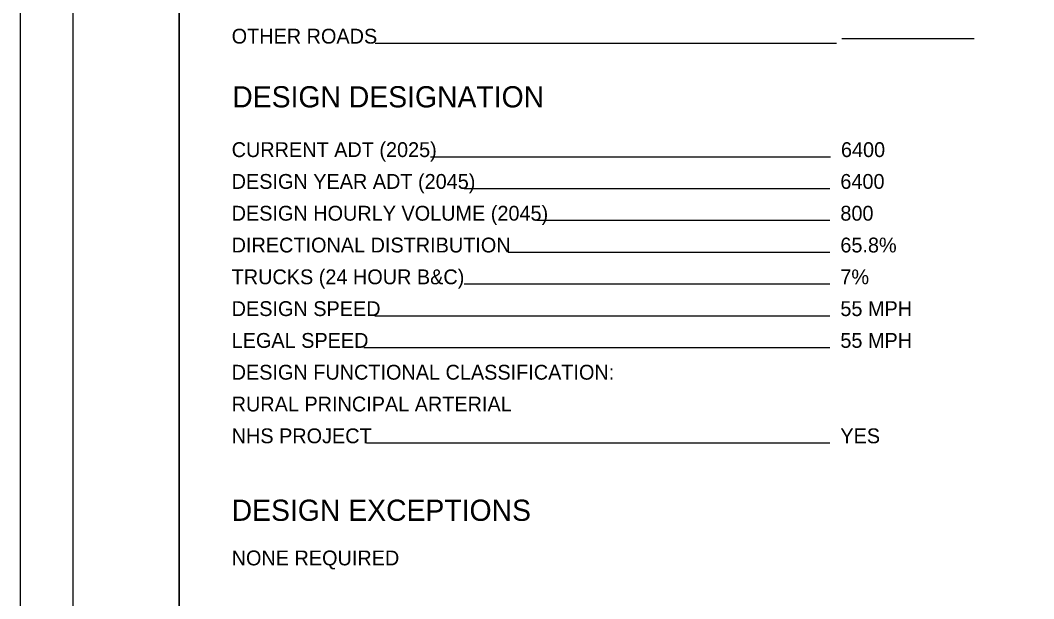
# Model space of a CAD drawing. Extents: x 21.4 to 65.3, y 4 to 26.
# Drawn here: x 21.45 to 31.01, y 9.59 to 15.05 of the extents above; entities that cross this region are included whole.
import ezdxf

# ---------------------------------------------------------------- set-up
doc = ezdxf.new("R2010")
doc.units = 0
for name, color, linetype in [('SH_Border', 7, 'Continuous'), ('SH_Cut_Line', 7, 'Continuous'), ('SH_Data', 7, 'Continuous'), ('SH_Text', 7, 'Continuous')]:
    doc.layers.add(name, color=color, linetype=linetype)

msp = doc.modelspace()

# ---------------------------------------------------------------- linework, layer by layer
at = {"layer": 'SH_Border'}
for points in [[(21.9473, 25.4542), (22.9473, 25.4542), (22.9473, 4.4542), (21.9473, 4.4542)], [(22.9473, 25.4542), (54.9473, 25.4542), (54.9473, 4.4542), (22.9473, 4.4542)]]:
    msp.add_lwpolyline(points, close=True, dxfattribs=at)
at = {"layer": 'SH_Cut_Line'}
msp.add_lwpolyline([(21.4473, 3.9542), (55.4473, 3.9542), (55.4473, 25.9542), (21.4473, 25.9542)], close=True, dxfattribs=at)
at = {"layer": 'SH_Data'}
for p, q in [((29.1473, 14.8308), (24.7944, 14.8308)), ((30.4473, 14.8765), (29.1973, 14.8765)), ((29.0897, 13.7604), (25.3183, 13.7604)), ((29.0842, 13.4604), (25.6358, 13.4604)), ((29.0842, 13.1604), (26.3196, 13.1604)), ((29.0842, 12.8604), (26.051, 12.8604)), ((29.0842, 12.5604), (25.6358, 12.5604)), ((29.0842, 12.2604), (24.7933, 12.2604)), ((29.0842, 11.9604), (24.6895, 11.9604)), ((29.0842, 11.0604), (24.7142, 11.0604))]:
    msp.add_line(p, q, dxfattribs=at)

# ---------------------------------------------------------------- texts
msp.add_text('DESIGN DESIGNATION', height=0.2, dxfattribs=at).set_placement((23.4473, 14.2288))
at = {"layer": 'SH_Text'}
for s, height, p in [('OTHER ROADS', 0.14, (23.4417, 14.8308)), ('CURRENT ADT (2025)', 0.14, (23.4417, 13.7604)), ('6400', 0.14, (29.1897, 13.7604)), ('DESIGN YEAR ADT (2045)', 0.14, (23.4417, 13.4604)), ('6400', 0.14, (29.1842, 13.4604)), ('DESIGN HOURLY VOLUME (2045)', 0.14, (23.4417, 13.1604)), ('800', 0.14, (29.1842, 13.1604)), ('DIRECTIONAL DISTRIBUTION', 0.14, (23.4417, 12.8604)), ('65.8%', 0.14, (29.1842, 12.8604)), ('TRUCKS (24 HOUR B&C)', 0.14, (23.4417, 12.5604)), ('7%', 0.14, (29.1842, 12.5604)), ('DESIGN SPEED', 0.14, (23.4417, 12.2604)), ('55 MPH', 0.14, (29.1842, 12.2604)), ('LEGAL SPEED', 0.14, (23.4417, 11.9604)), ('55 MPH', 0.14, (29.1842, 11.9604)), ('DESIGN FUNCTIONAL CLASSIFICATION:', 0.14, (23.4417, 11.6604)), ('RURAL PRINCIPAL ARTERIAL', 0.14, (23.4417, 11.3604)), ('NHS PROJECT', 0.14, (23.4417, 11.0604)), ('YES', 0.14, (29.1842, 11.0604)), ('DESIGN EXCEPTIONS', 0.2, (23.4417, 10.3285)), ('NONE REQUIRED', 0.14, (23.4417, 9.9085))]:
    msp.add_text(s, height=height, dxfattribs=at).set_placement(p)

doc.saveas('drawing.dxf')
